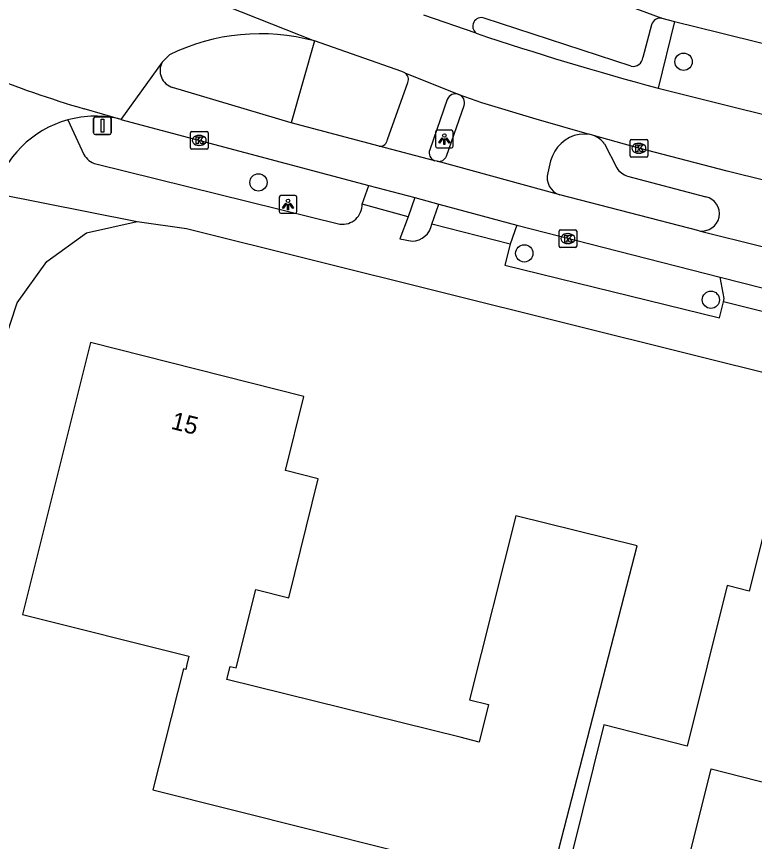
# Model space of a CAD drawing. Extents: x 161141 to 161601, y 381708 to 382245.
# Drawn here: x 161380.23 to 161421.99, y 382150.57 to 382197.24 of the extents above; entities that cross this region are included whole.
import ezdxf

# ---------------------------------------------------------------- set-up
doc = ezdxf.new("R2010")
doc.units = 0
for name, color, linetype in [('IMGEO_Boom', 7, 'Continuous'), ('IMGEO_Fietspad_gesloten', 7, 'Continuous'), ('IMGEO_Kolk', 7, 'Continuous'), ('IMGEO_Lichtpunt', 7, 'Continuous'), ('IMGEO_Muur', 7, 'Continuous'), ('IMGEO_Pand', 7, 'Continuous'), ('IMGEO_Pand_nummerreeks', 7, 'Continuous'), ('IMGEO_Parkeervlak_open', 7, 'Continuous'), ('IMGEO_Rijbaan_lokaal_gesloten', 7, 'Continuous'), ('IMGEO_Rijbaan_lokaal_open', 7, 'Continuous'), ('IMGEO_Verkeersbordpaal', 7, 'Continuous'), ('IMGEO_Verkeerseiland_open', 7, 'Continuous'), ('IMGEO_Voetpad_open', 7, 'Continuous')]:
    doc.layers.add(name, color=color, linetype=linetype)

msp = doc.modelspace()

# ---------------------------------------------------------------- linework, layer by layer
at = {"layer": 'IMGEO_Boom'}
for centre in [(161417.973, 382194.68), (161393.919, 382187.856), (161408.961, 382183.841), (161419.516, 382181.215)]:
    msp.add_circle(centre, 0.489, dxfattribs=at)
at = {"layer": 'IMGEO_Fietspad_gesloten'}
for points in [[(161395.77, 382191.23), (161389.063, 382193.224)], [(161386.139, 382191.421), (161400.157, 382187.686)], [(161400.753, 382189.896), (161395.77, 382191.23)], [(161403.898, 382189.082), (161400.753, 382189.896)], [(161404.025, 382189.049), (161403.898, 382189.082)], [(161410.964, 382187.154), (161404.025, 382189.049)], [(161400.157, 382187.686), (161402.771, 382186.995)], [(161402.771, 382186.995), (161404.125, 382186.632)], [(161418.85, 382185.12), (161410.964, 382187.154)], [(161404.125, 382186.632), (161408.543, 382185.44)], [(161408.543, 382185.44), (161420.035, 382182.5)], [(161418.85, 382185.12), (161426.145, 382183.304)], [(161420.035, 382182.5), (161423.68, 382181.579)]]:
    msp.add_lwpolyline(points, dxfattribs=at)
msp.add_arc((161389.344, 382194.18), 0.997, 151.1111, 253.6412, dxfattribs=at)
at = {"layer": 'IMGEO_Kolk'}
for p, q in [((161390.14, 382190.73), (161390.992, 382190.73)), ((161390.065, 382189.804), (161390.065, 382190.656)), ((161390.553, 382190.51), (161390.578, 382190.51)), ((161391.066, 382190.656), (161391.066, 382189.804)), ((161415.019, 382190.284), (161415.871, 382190.284)), ((161390.576, 382189.95), (161390.551, 382189.95)), ((161414.944, 382189.358), (161414.944, 382190.21)), ((161415.432, 382190.064), (161415.457, 382190.064)), ((161415.945, 382190.21), (161415.945, 382189.358)), ((161390.992, 382189.73), (161390.14, 382189.73)), ((161415.455, 382189.504), (161415.43, 382189.504)), ((161415.871, 382189.284), (161415.019, 382189.284)), ((161411, 382185.176), (161411.852, 382185.176)), ((161410.925, 382184.25), (161410.925, 382185.102)), ((161411.413, 382184.956), (161411.438, 382184.956)), ((161411.926, 382185.102), (161411.926, 382184.25)), ((161411.852, 382184.176), (161411, 382184.176)), ((161411.436, 382184.396), (161411.411, 382184.396))]:
    msp.add_line(p, q, dxfattribs=at)
for points in [[(161390.14, 382190.73), (161390.992, 382190.73)], [(161390.065, 382189.804), (161390.065, 382190.656)], [(161390.386, 382190.43), (161390.509, 382190.43), (161390.509, 382190.279), (161390.639, 382190.43), (161390.803, 382190.43), (161390.657, 382190.279), (161390.81, 382190.03), (161390.658, 382190.03), (161390.573, 382190.194), (161390.509, 382190.127), (161390.509, 382190.03), (161390.386, 382190.03), (161390.386, 382190.43)], [(161391.066, 382190.656), (161391.066, 382189.804)], [(161415.019, 382190.284), (161415.871, 382190.284)], [(161414.944, 382189.358), (161414.944, 382190.21)], [(161415.265, 382189.984), (161415.388, 382189.984), (161415.388, 382189.833), (161415.518, 382189.984), (161415.682, 382189.984), (161415.536, 382189.833), (161415.689, 382189.584), (161415.537, 382189.584), (161415.452, 382189.748), (161415.388, 382189.681), (161415.388, 382189.584), (161415.265, 382189.584), (161415.265, 382189.984)], [(161415.945, 382190.21), (161415.945, 382189.358)], [(161390.992, 382189.73), (161390.14, 382189.73)], [(161415.871, 382189.284), (161415.019, 382189.284)], [(161411, 382185.176), (161411.852, 382185.176)], [(161410.925, 382184.25), (161410.925, 382185.102)], [(161411.246, 382184.876), (161411.369, 382184.876), (161411.369, 382184.725), (161411.499, 382184.876), (161411.663, 382184.876), (161411.517, 382184.725), (161411.67, 382184.476), (161411.518, 382184.476), (161411.433, 382184.64), (161411.369, 382184.573), (161411.369, 382184.476), (161411.246, 382184.476), (161411.246, 382184.876)], [(161411.926, 382185.102), (161411.926, 382184.25)], [(161411.852, 382184.176), (161411, 382184.176)]]:
    msp.add_lwpolyline(points, dxfattribs=at)
for centre, start, end in [((161390.142, 382190.654), 91.552, 178.448), ((161390.142, 382190.654), 91.552, 178.448), ((161390.99, 382190.654), 1.552, 88.448), ((161390.99, 382190.654), 1.552, 88.448), ((161415.021, 382190.208), 91.552, 178.448), ((161415.021, 382190.208), 91.552, 178.448), ((161415.869, 382190.208), 1.552, 88.448), ((161415.869, 382190.208), 1.552, 88.448), ((161390.142, 382189.806), 181.552, 268.448), ((161390.142, 382189.806), 181.552, 268.448), ((161390.99, 382189.806), 271.552, 358.448), ((161390.99, 382189.806), 271.552, 358.448), ((161415.021, 382189.36), 181.552, 268.448), ((161415.021, 382189.36), 181.552, 268.448), ((161415.869, 382189.36), 271.552, 358.448), ((161415.869, 382189.36), 271.552, 358.448), ((161411.002, 382185.1), 91.552, 178.448), ((161411.002, 382185.1), 91.552, 178.448), ((161411.85, 382185.1), 1.552, 88.448), ((161411.85, 382185.1), 1.552, 88.448), ((161411.002, 382184.252), 181.552, 268.448), ((161411.002, 382184.252), 181.552, 268.448), ((161411.85, 382184.252), 271.552, 358.448), ((161411.85, 382184.252), 271.552, 358.448)]:
    msp.add_arc(centre, 0.0765, start, end, dxfattribs=at)
for centre, major_axis, ratio, start_param, end_param in [((161390.552, 382190.23), (-0.387, 0.002), 0.722429, 4.712389, 7.853982), ((161390.577, 382190.23), (-0.39, 0.002), 0.717154, 1.570796, 4.712389), ((161415.431, 382189.784), (-0.387, 0.002), 0.722429, 4.712389, 7.853982), ((161415.456, 382189.784), (-0.39, 0.002), 0.717154, 1.570796, 4.712389), ((161411.412, 382184.676), (-0.387, 0.002), 0.722429, 4.712389, 7.853982), ((161411.437, 382184.676), (-0.39, 0.002), 0.717154, 1.570796, 4.712389)]:
    msp.add_ellipse(centre, major_axis=major_axis, ratio=ratio, start_param=start_param, end_param=end_param, dxfattribs=at)
at = {"layer": 'IMGEO_Lichtpunt'}
for p, q in [((161403.937, 382190.707), (161403.937, 382189.9)), ((161403.937, 382190.707), (161403.937, 382189.9)), ((161404.839, 382190.802), (161404.031, 382190.802)), ((161404.839, 382190.802), (161404.031, 382190.802)), ((161404.933, 382189.9), (161404.933, 382190.707)), ((161404.933, 382189.9), (161404.933, 382190.707)), ((161404.031, 382189.806), (161404.839, 382189.806)), ((161404.031, 382189.806), (161404.839, 382189.806)), ((161395.093, 382187.011), (161395.093, 382186.204)), ((161395.093, 382187.011), (161395.093, 382186.204)), ((161395.995, 382187.106), (161395.187, 382187.106)), ((161395.995, 382187.106), (161395.187, 382187.106)), ((161396.089, 382186.204), (161396.089, 382187.011)), ((161396.089, 382186.204), (161396.089, 382187.011)), ((161395.187, 382186.11), (161395.995, 382186.11)), ((161395.187, 382186.11), (161395.995, 382186.11))]:
    msp.add_line(p, q, dxfattribs=at)
for points in [[(161404.311, 382190.371), (161404.35, 382190.343), (161404.162, 382190.081), (161404.124, 382190.108), (161404.311, 382190.371)], [(161404.413, 382190.323), (161404.46, 382190.323), (161404.46, 382190.001), (161404.413, 382190.001), (161404.413, 382190.323)], [(161404.523, 382190.343), (161404.561, 382190.37), (161404.748, 382190.108), (161404.709, 382190.08), (161404.523, 382190.343)], [(161395.467, 382186.675), (161395.506, 382186.647), (161395.318, 382186.385), (161395.28, 382186.412), (161395.467, 382186.675)], [(161395.569, 382186.627), (161395.616, 382186.627), (161395.616, 382186.305), (161395.569, 382186.305), (161395.569, 382186.627)], [(161395.679, 382186.647), (161395.717, 382186.674), (161395.904, 382186.412), (161395.865, 382186.384), (161395.679, 382186.647)]]:
    msp.add_lwpolyline(points, dxfattribs=at)
for centre in [(161404.436, 382190.505), (161395.592, 382186.809)]:
    msp.add_circle(centre, 0.0994, dxfattribs=at)
for centre, start, end in [((161404.031, 382190.707), 90, 180), ((161404.031, 382190.707), 90, 180), ((161404.839, 382190.707), 0, 90), ((161404.839, 382190.707), 0, 90), ((161404.031, 382189.9), 180, 270), ((161404.031, 382189.9), 180, 270), ((161404.839, 382189.9), 270, 0), ((161404.839, 382189.9), 270, 360), ((161395.187, 382187.011), 90, 180), ((161395.187, 382187.011), 90, 180), ((161395.995, 382187.011), 0, 90), ((161395.995, 382187.011), 0, 90), ((161395.187, 382186.204), 180, 270), ((161395.187, 382186.204), 180, 270), ((161395.995, 382186.204), 270, 0), ((161395.995, 382186.204), 270, 360)]:
    msp.add_arc(centre, 0.0946, start, end, dxfattribs=at)
at = {"layer": 'IMGEO_Muur'}
msp.add_lwpolyline([(161365.084, 382143.565), (161369.98, 382153.637), (161372.26, 382158.835), (161374.321, 382163.969), (161377.586, 382172.934), (161380.259, 382181.034), (161381.949, 382183.375), (161384.186, 382184.996), (161387.058, 382185.651), (161389.844, 382185.251), (161418.52, 382178.097)], dxfattribs=at)
at = {"layer": 'IMGEO_Pand'}
for points in [[(161405.328, 382156.469), (161392.128, 382159.743), (161392.312, 382160.48), (161392.661, 382160.393), (161393.766, 382164.828), (161395.629, 382164.363), (161397.305, 382171.088), (161395.44, 382171.566), (161396.492, 382175.746), (161384.415, 382178.79), (161380.562, 382163.42), (161389.977, 382161.049), (161389.869, 382160.579), (161389.809, 382160.312), (161389.667, 382160.348), (161387.933, 382153.493), (161410.333, 382147.872), (161415.348, 382167.296), (161408.489, 382169.001), (161405.861, 382158.583), (161406.93, 382158.318), (161406.405, 382156.202), (161405.328, 382156.469)], [(161428.705, 382161.861), (161429.913, 382166.712), (161428.484, 382167.068), (161428.734, 382168.071), (161426.329, 382168.67), (161426.089, 382167.707), (161422.647, 382168.564), (161421.693, 382164.734), (161420.44, 382165.046), (161418.18, 382155.968), (161413.467, 382157.169), (161412.259, 382152.318), (161410.912, 382146.912), (161417.202, 382145.309), (161419.537, 382154.683), (161426.476, 382152.914), (161428.705, 382161.861)]]:
    msp.add_lwpolyline(points, dxfattribs=at)
at = {"layer": 'IMGEO_Parkeervlak_open'}
for points in [[(161413.5, 382190.042), (161414.192, 382188.674)], [(161414.806, 382188.21), (161419.229, 382187.043)]]:
    msp.add_lwpolyline(points, dxfattribs=at)
for centre, radius, start, end in [((161412.352, 382189.148), 1.455, 37.8839, 68.7901), ((161415.129, 382189.276), 1.114, 212.7057, 253.1376), ((161419.022, 382186.085), 0.98, 259.8686, 77.8326)]:
    msp.add_arc(centre, radius, start, end, dxfattribs=at)
at = {"layer": 'IMGEO_Rijbaan_lokaal_gesloten'}
for points in [[(161371.295, 382209.7), (161379.73, 382204.16), (161385.013, 382201.164), (161389.691, 382198.806), (161397.081, 382195.854)], [(161413.629, 382198.305), (161416.752, 382197.147)], [(161406.237, 382196.29), (161403.28, 382197.317)], [(161416.752, 382197.147), (161417.456, 382196.964)], [(161417.456, 382196.964), (161420.058, 382196.306), (161460.894, 382186.197), (161500, 382176.547), (161558.491, 382162.113), (161560.838, 382161.565), (161562.428, 382161.253), (161571.347, 382159.936), (161575.364, 382159.517)], [(161402.198, 382194.055), (161402.036, 382194.12), (161397.081, 382195.854)], [(161388.471, 382194.662), (161388.88, 382195.063)], [(161388.471, 382194.662), (161386.139, 382191.421)], [(161402.198, 382194.055), (161405.248, 382192.835)], [(161416.542, 382193.184), (161418.72, 382192.635), (161459.898, 382182.379), (161500, 382172.465), (161568.862, 382155.44)], [(161405.248, 382192.835), (161406.546, 382192.371), (161409.616, 382191.449), (161412.637, 382190.575)], [(161386.139, 382191.421), (161384.063, 382192.014)], [(161412.878, 382190.505), (161412.768, 382190.537), (161412.637, 382190.575)], [(161571.771, 382151.019), (161502.587, 382168.125), (161500, 382168.766), (161459.102, 382178.908), (161420.449, 382188.487), (161415.442, 382189.785), (161412.878, 382190.505)]]:
    msp.add_lwpolyline(points, dxfattribs=at)
for centre, radius, start, end in [((161402.679, 382255.054), 65.731, 243.04218, 253.54772), ((161394.025, 382184.632), 11.631, 74.7652, 116.2532), ((161461.322, 382360.402), 173.11, 251.44538, 255.00826)]:
    msp.add_arc(centre, radius, start, end, dxfattribs=at)
at = {"layer": 'IMGEO_Rijbaan_lokaal_open'}
for centre, radius, start, end in [((161384.695, 382185.661), 5.939, 105.346, 164.5297), ((161384.694, 382185.656), 5.944, 75.9283, 105.3255)]:
    msp.add_arc(centre, radius, start, end, dxfattribs=at)
at = {"layer": 'IMGEO_Verkeersbordpaal'}
for p, q in [((161384.59, 382190.663), (161384.59, 382191.463)), ((161384.59, 382191.463), (161384.59, 382190.663)), ((161384.69, 382191.563), (161385.48, 382191.563)), ((161385.48, 382191.563), (161384.69, 382191.563)), ((161385.58, 382191.463), (161385.58, 382190.663)), ((161385.58, 382190.663), (161385.58, 382191.463)), ((161385.48, 382190.563), (161384.69, 382190.563)), ((161384.69, 382190.563), (161385.48, 382190.563))]:
    msp.add_line(p, q, dxfattribs=at)
msp.add_lwpolyline([(161385.01, 382191.438), (161385.16, 382191.438), (161385.16, 382190.688), (161385.01, 382190.688), (161385.01, 382191.438)], dxfattribs=at)
for centre, start, end in [((161384.69, 382191.463), 90, 180), ((161384.69, 382191.463), 90, 180), ((161385.48, 382191.463), 0, 90), ((161385.48, 382191.463), 360, 90), ((161384.69, 382190.663), 180, 270), ((161384.69, 382190.663), 180, 270), ((161385.48, 382190.663), 270, 0), ((161385.48, 382190.663), 270, 0)]:
    msp.add_arc(centre, 0.1, start, end, dxfattribs=at)
at = {"layer": 'IMGEO_Verkeerseiland_open'}
for points in [[(161417.456, 382196.964), (161416.542, 382193.184)], [(161397.081, 382195.854), (161395.77, 382191.23)]]:
    msp.add_lwpolyline(points, dxfattribs=at)
at = {"layer": 'IMGEO_Voetpad_open'}
for points in [[(161415.009, 382194.421), (161406.697, 382197.146)], [(161416.157, 382196.766), (161415.674, 382194.913)], [(161401.211, 382190.284), (161402.364, 382193.499)], [(161404.599, 382192.547), (161403.606, 382189.703)], [(161404.555, 382189.347), (161405.556, 382192.197)], [(161383.123, 382191.388), (161384.037, 382189.44)], [(161412.637, 382190.575), (161412.068, 382190.572)], [(161384.721, 382188.897), (161398.528, 382185.5)], [(161410.452, 382189.082), (161410.292, 382188.402)], [(161399.787, 382186.631), (161400.157, 382187.686)], [(161378.971, 382187.245), (161387.058, 382185.651)], [(161402.771, 382186.995), (161402.397, 382185.906)], [(161402.397, 382185.906), (161399.787, 382186.631)], [(161403.727, 382185.497), (161404.125, 382186.632)], [(161365.084, 382143.565), (161369.98, 382153.637), (161372.26, 382158.835), (161374.321, 382163.969), (161377.586, 382172.934), (161380.259, 382181.034), (161381.949, 382183.375), (161384.186, 382184.996), (161387.058, 382185.651)], [(161387.058, 382185.651), (161389.844, 382185.251), (161418.52, 382178.097), (161457.897, 382168.303), (161477.956, 382163.494), (161500, 382158.072), (161544.61, 382147.101), (161553.295, 382144.911), (161577.621, 382138.939), (161579.137, 382138.37)], [(161402.397, 382185.906), (161401.916, 382184.669), (161402.608, 382184.522)], [(161408.169, 382184.367), (161403.727, 382185.497)], [(161408.543, 382185.44), (161408.169, 382184.367)], [(161408.169, 382184.367), (161407.86, 382183.171), (161419.997, 382180.199), (161420.225, 382181.103)], [(161420.225, 382181.103), (161420.271, 382181.292), (161420.035, 382182.5)], [(161423.245, 382180.339), (161420.225, 382181.103)]]:
    msp.add_lwpolyline(points, dxfattribs=at)
for centre, radius, start, end in [((161406.532, 382196.683), 0.491, 70.3528, 233.1415), ((161416.678, 382196.608), 0.544, 82.1598, 163.106), ((161415.108, 382194.983), 0.57, 259.9947, 352.9971), ((161401.953, 382193.679), 0.449, 336.3718, 56.8753), ((161405.073, 382192.355), 0.511, 69.9207, 157.9388), ((161405.072, 382192.357), 0.51, 341.767, 69.7717), ((161400.786, 382190.321), 0.427, 265.5581, 354.9818), ((161412.431, 382188.556), 2.048, 100.2227, 165.1313), ((161385.009, 382189.963), 1.104, 208.2546, 254.8561), ((161404.048, 382189.532), 0.474, 158.813, 251.5537), ((161404.114, 382189.511), 0.47, 259.0634, 339.6316), ((161411.278, 382188.128), 1.024, 164.4866, 252.1149), ((161398.677, 382186.6), 1.11, 262.267, 1.6018), ((161402.57, 382185.695), 1.174, 271.8463, 350.2859)]:
    msp.add_arc(centre, radius, start, end, dxfattribs=at)

# ---------------------------------------------------------------- texts
at = {"layer": 'IMGEO_Pand_nummerreeks'}
msp.add_text('15', height=1, rotation=346.015, dxfattribs=at).set_placement((161388.916, 382173.928))

doc.saveas('drawing.dxf')
